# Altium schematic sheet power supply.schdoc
size 302 x 131 mm
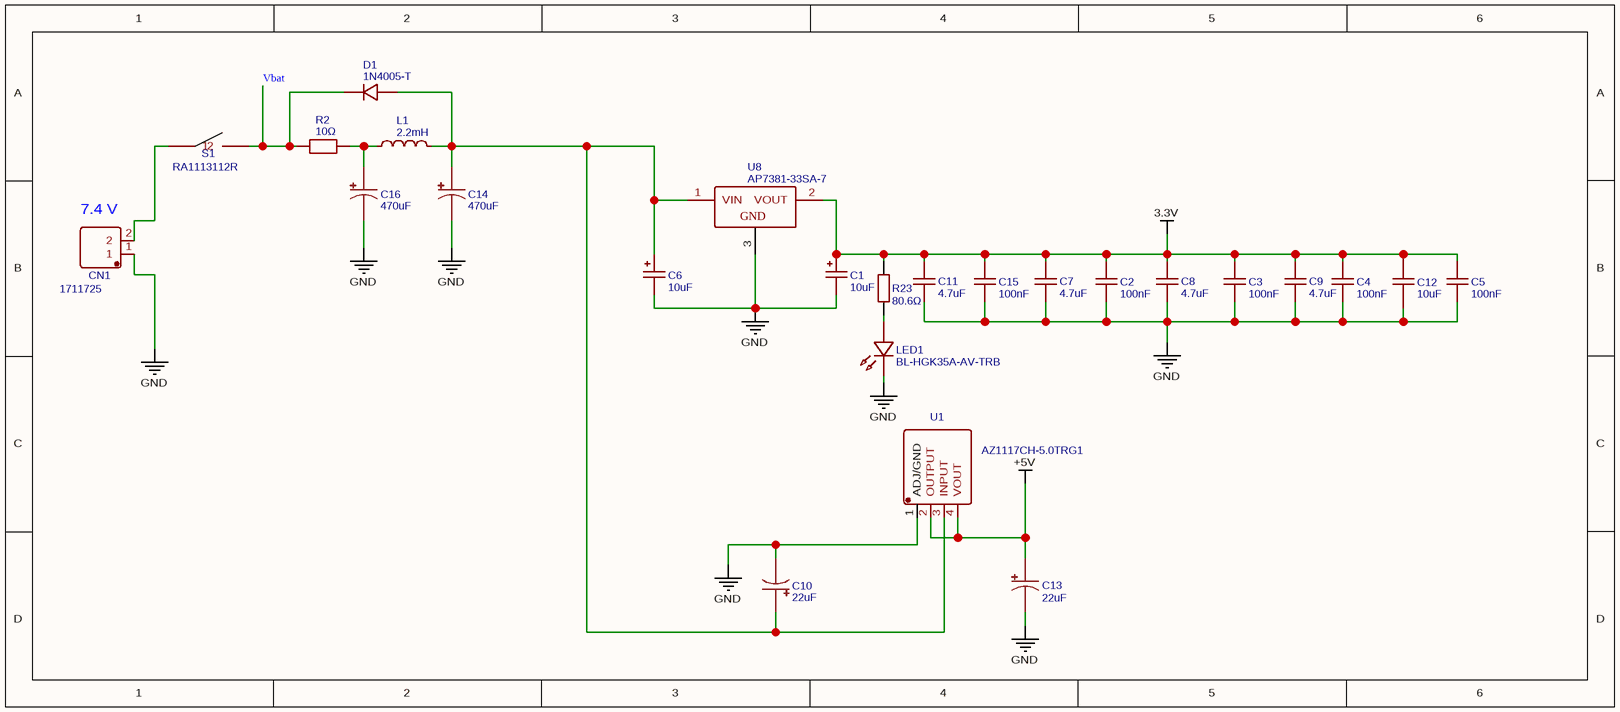
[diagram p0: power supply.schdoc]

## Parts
C1  10uF  [CAP-SMD_L3.2-W1.6-RD-C7171]
C2  100nF  [C1206]
C3  100nF  [C1206]
C4  100nF  [C1206]
C5  100nF  [C1206]
C6  10uF  [CAP-SMD_L3.2-W1.6-RD-C7171]
C7  4.7uF  [C1206]
C8  4.7uF  [C1206]
C9  4.7uF  [C1206]
C10  22uF  [CAP-SMD_L3.5-W2.8-R-RD]
C11  4.7uF  [C1206]
C12  10uF  [C0603]
C13  22uF  [CAP-SMD_L3.5-W2.8-R-RD]
C14  470uF  [CAP-TH_BD8.0-P3.50-D0.6-FD]
C15  100nF  [C1206]
C16  470uF  [CAP-TH_BD8.0-P3.50-D0.6-FD]
CN1  1711725  [CONN-TH_MKDS3-2-5.08]
D1  1N4005-T  [DO-41_BD2.4-L4.7-P8.70-D0.9-RD]
L1  2.2mH  [IND-TH_BD9.5-P5.20-D0.6]
LED1  BL-HGK35A-AV-TRB  [LED0805-RD_GREEN]
R2  10Ω  [R1210]
R23  80.6Ω  [R0402]
S1  RA1113112R  [SWITCH-2PIN]
U1  AZ1117CH-5.0TRG1  [SOT-223_L6.5-W3.5-P2.30-LS7.0-BR]
U8  AP7381-33SA-7  [SOT-23-3_L2.9-W1.3-P1.90-LS2.4-BR]

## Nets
3.3V: C1.1 C2.2 C3.2 C4.2 C5.2 C7.1 C8.1 C9.1 C11.1 C12.2 C15.2 R23.2 U8.2(VOUT)
+5V: C13.1 U1.2(OUTPUT) U1.4(VOUT)
GND: C1.2 C2.1 C3.1 C4.1 C5.1 C6.2 C7.2 C8.2 C9.2 C10.2 C11.2 C12.1 C13.2 C14.2 C15.1 C16.2 CN1.1 LED1.1(K) U1.1(ADJ/GND) U8.3(GND)
Vbat: D1.1 R2.1 S1.2
NetC6_1: C6.1 C10.1 C14.1 D1.2 L1.2 U1.3(INPUT) U8.1(VIN)
NetC16_1: C16.1 L1.1 R2.2
NetCN1_2: CN1.2 S1.1
NetLED1_2: LED1.2(A) R23.1

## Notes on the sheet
- (near CN1) 7.4 V

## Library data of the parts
C1 C6 = 10uF: Manufacturer: Kyocera AVX; Manufacturer Part: TAJA106K016RNJ; nameAlias: Value
C2-C5 C15 = 100nF: Manufacturer Part: CL31B104KBCNNNC; Manufacturer: SAMSUNG(三星); nameAlias: Value
C7-C9 C11 = 4.7uF: Manufacturer: FH(风华); Manufacturer Part: 1206B475K500NT; nameAlias: Value
C10 C13 = 22uF: Manufacturer: Kyocera AVX; Manufacturer Part: TPSB226K020R0400; nameAlias: Value; Contributor: LCSC
C12 = 10uF: Manufacturer: SAMSUNG(三星); Manufacturer Part: CL10A106MA8NRNC; nameAlias: Value
C14 C16 = 470uF: Manufacturer: lelon(立隆); Manufacturer Part: RXW471M1CBK-0815; nameAlias: Value; Contributor: LCSC
CN1 = 1711725: Manufacturer: Phoenix Contact(菲尼克斯)
D1 = 1N4005-T: Manufacturer: DIODES(美台); Contributor: LCSC
L1 = 2.2mH: Manufacturer: PROD(谱罗德); Manufacturer Part: PDPTAT0810-222K; Contributor: lcsc; nameAlias: Value
LED1 = BL-HGK35A-AV-TRB: Manufacturer: BrtLed(佰鸿); Contributor: lcsc
R2 = 10Ω: Manufacturer: YAGEO(国巨); Manufacturer Part: AC1210JR-0710RL; Contributor: LCSC; nameAlias: Value
R23 = 80.6Ω: Manufacturer: LIZ(丽智电子); Manufacturer Part: CR0402FF80R6G; nameAlias: Value
S1 = RA1113112R: Manufacturer: E-Switch; Contributor: miclol
U1 = AZ1117CH-5.0TRG1: Manufacturer: DIODES(美台); Contributor: LCSC
U8 = AP7381-33SA-7: Manufacturer: DIODES(美台); Contributor: lcsc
